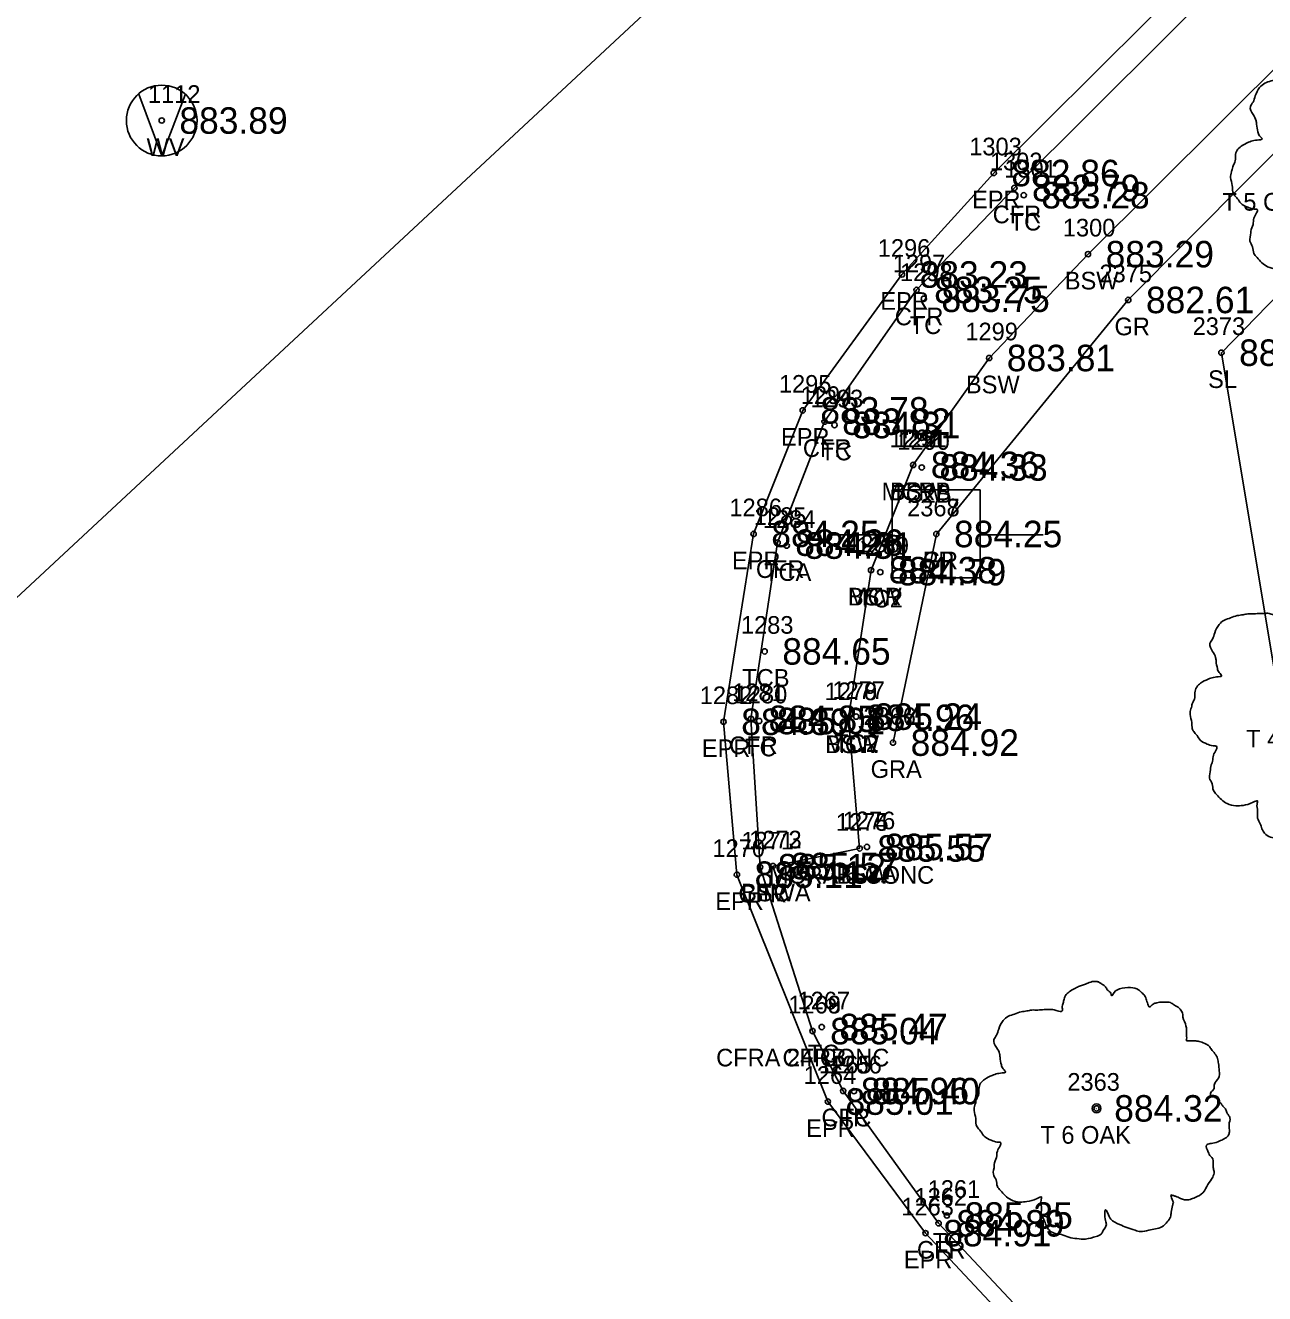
# Model space of a CAD drawing. Extents: x 1622501 to 1626664, y 1117816 to 1121579.
# Drawn here: x 1623634 to 1623704.2, y 1118887.8 to 1118959.6 of the extents above; entities that cross this region are included whole.
import ezdxf

# ---------------------------------------------------------------- set-up
doc = ezdxf.new("R2010")
doc.units = 0
for name, color, linetype in [('RD_EX_Conc', 7, 'Continuous'), ('RD_EX_Conc_txCode', 7, 'Continuous'), ('RD_EX_GuardRail', 7, 'Continuous'), ('RD_EX_GuardRail_txCode', 7, 'Continuous'), ('RD_EX_Road', 7, 'Continuous'), ('RD_EX_Road_txCode', 7, 'Continuous'), ('RD_EX_TX_Conc_ELEV', 7, 'Continuous'), ('RD_EX_TX_GuardRail_ELEV', 7, 'Continuous'), ('RD_EX_TX_Road_ELEV', 7, 'Continuous'), ('RD_EX_TX_UT_ELEV', 7, 'Continuous'), ('RD_EX_TX_VEG_ELEV', 7, 'Continuous'), ('RD_EX_UT', 7, 'Continuous'), ('RD_EX_UT_txCode', 7, 'Continuous'), ('RD_EX_VEG', 7, 'Continuous'), ('RD_EX_VEG_txCode', 7, 'Continuous'), ('RD_HC_Cl', 7, 'Continuous'), ('RD_HC_Survey_ELEV', 7, 'Continuous'), ('RD_SMD_Locator', 7, 'Continuous')]:
    doc.layers.add(name, color=color, linetype=linetype)

msp = doc.modelspace()

# ---------------------------------------------------------------- linework, layer by layer
at = {"layer": 'RD_EX_Conc'}
for points in [[(1623723.663, 1118851.276), (1623685.686, 1118891.781), (1623680.278, 1118899.276), (1623678.543, 1118902.667), (1623678.543, 1118902.667), (1623675.573, 1118911.952), (1623675.054, 1118920.354), (1623676.566, 1118930.331), (1623679.225, 1118937.184), (1623684.435, 1118944.641), (1623689.976, 1118950.418), (1623724.501, 1118984.8), (1623759.009, 1119020.42), (1623793.698, 1119055.906), (1623829.35, 1119090.862), (1623865.612, 1119125.129), (1623901.916, 1119159.181), (1623933.224, 1119188.498)], [(1623676.299, 1118912.014), (1623681.213, 1118913.011), (1623680.576, 1118920.41), (1623681.86, 1118928.773), (1623684.243, 1118934.734), (1623688.548, 1118940.788), (1623694.147, 1118946.67), (1623728.265, 1118980.628), (1623762.622, 1119016.068), (1623797.565, 1119051.919), (1623833.104, 1119086.631), (1623869.148, 1119120.8), (1623905.547, 1119154.999), (1623936.969, 1119184.346), (1623933.79, 1119188.026)], [(1623681.213, 1118913.011), (1623680.576, 1118920.41), (1623681.86, 1118928.773), (1623684.243, 1118934.734)]]:
    msp.add_lwpolyline(points, dxfattribs=at)
at = {"layer": 'RD_EX_GuardRail'}
msp.add_lwpolyline([(1623683.102, 1118919.005), (1623685.557, 1118930.82), (1623696.428, 1118944.075), (1623730.666, 1118978.537), (1623766.322, 1119014.094)], dxfattribs=at)
at = {"layer": 'RD_EX_Road'}
msp.add_lwpolyline([(1623722.97, 1118850.612), (1623684.945, 1118891.225), (1623679.413, 1118898.675), (1623674.261, 1118911.526), (1623673.503, 1118920.185), (1623675.206, 1118930.826), (1623677.985, 1118937.822), (1623683.61, 1118945.518), (1623688.806, 1118951.265), (1623723.469, 1118985.717), (1623758.003, 1119021.43), (1623792.693, 1119056.92), (1623828.408, 1119091.915), (1623864.599, 1119126.191), (1623900.882, 1119160.216), (1623932.37, 1119189.416), (1623932.628, 1119189.219), (1623935.818, 1119192.17), (1623973.771, 1119227.767), (1623990.875, 1119243.538), (1624009.987, 1119262.018), (1624046.295, 1119296.153)], dxfattribs=at)
at = {"layer": 'RD_EX_UT'}
for p, q in [((1623641.68, 1118952.244), (1623640.376, 1118955.727)), ((1623641.68, 1118952.244), (1623643.002, 1118955.689)), ((1623688.047, 1118933.329), (1623683.047, 1118933.329)), ((1623683.047, 1118933.329), (1623683.047, 1118928.329)), ((1623688.047, 1118928.329), (1623688.047, 1118933.329)), ((1623679.616, 1118930.767), (1623683.086, 1118930.767)), ((1623687.976, 1118930.767), (1623691.616, 1118930.767)), ((1623683.047, 1118928.329), (1623688.047, 1118928.329))]:
    msp.add_line(p, q, dxfattribs=at)
msp.add_circle((1623641.68, 1118954.237), 2, dxfattribs=at)
at = {"layer": 'RD_EX_VEG'}
msp.add_lwpolyline([(1623719.641, 1118895.843), (1623705.963, 1118915.58), (1623701.704, 1118941.089), (1623733.735, 1118974.045), (1623762.596, 1118998.968), (1623764.149, 1118997.606), (1623773.667, 1119008.214), (1623809.616, 1119040.562), (1623866.904, 1119093.207), (1623868.266, 1119096.09), (1623881.794, 1119107.882), (1623919.645, 1119143.849), (1623945.126, 1119165.729), (1623961.583, 1119122.835), (1623970.119, 1119088.038)], dxfattribs=at)
for centre, radius in [((1623694.631, 1118898.29), 0.25), ((1623694.618, 1118898.271), 0.0001)]:
    msp.add_circle(centre, radius, dxfattribs=at)
for points in [[(1623709.292, 1118958.301), (1623708.992, 1118958.326), (1623708.668, 1118958.226), (1623708.418, 1118958.126), (1623708.193, 1118958.051), (1623707.968, 1118957.951), (1623707.668, 1118957.776), (1623707.443, 1118957.576), (1623707.318, 1118957.326), (1623707.268, 1118957.102), (1623707.218, 1118956.827), (1623707.218, 1118956.652), (1623707.093, 1118956.627), (1623706.943, 1118956.652), (1623706.693, 1118956.727), (1623706.444, 1118956.727), (1623706.194, 1118956.727), (1623705.844, 1118956.702), (1623705.494, 1118956.702), (1623705.219, 1118956.652), (1623704.894, 1118956.602), (1623704.519, 1118956.477), (1623704.17, 1118956.352), (1623703.87, 1118956.102), (1623703.62, 1118955.627), (1623703.495, 1118955.277), (1623703.345, 1118955.027), (1623703.495, 1118954.578), (1623703.67, 1118954.228), (1623703.695, 1118954.028), (1623703.77, 1118953.603), (1623703.87, 1118953.378), (1623703.995, 1118953.178), (1623703.92, 1118953.153), (1623703.545, 1118953.103), (1623703.245, 1118953.003), (1623702.82, 1118952.778), (1623702.595, 1118952.554), (1623702.495, 1118952.229), (1623702.47, 1118951.879), (1623702.37, 1118951.679), (1623702.295, 1118951.404), (1623702.27, 1118951.329), (1623702.22, 1118951.004), (1623702.32, 1118950.554), (1623702.345, 1118950.205), (1623702.47, 1118949.98), (1623702.62, 1118949.805), (1623702.795, 1118949.555), (1623703.195, 1118949.33), (1623703.52, 1118949.23), (1623703.72, 1118949.205), (1623703.545, 1118948.705), (1623703.495, 1118948.355), (1623703.37, 1118947.956), (1623703.37, 1118947.881), (1623703.32, 1118947.406), (1623703.47, 1118947.081), (1623703.545, 1118946.706), (1623703.72, 1118946.481), (1623703.995, 1118946.181), (1623704.319, 1118945.956), (1623704.819, 1118945.831), (1623705.219, 1118945.856), (1623705.794, 1118946.031), (1623706.044, 1118946.106), (1623706.019, 1118945.931), (1623706.044, 1118945.557), (1623706.044, 1118945.132), (1623706.194, 1118944.807), (1623706.294, 1118944.532), (1623706.444, 1118944.282), (1623706.768, 1118944.057), (1623707.168, 1118943.982), (1623707.593, 1118943.832), (1623708.043, 1118943.757), (1623708.543, 1118943.732), (1623709.142, 1118943.882), (1623709.417, 1118944.007), (1623709.517, 1118944.182), (1623709.717, 1118944.557), (1623709.667, 1118944.782), (1623709.692, 1118945.382), (1623709.792, 1118945.207), (1623709.967, 1118944.857), (1623710.467, 1118944.557), (1623710.867, 1118944.382), (1623711.341, 1118944.232), (1623711.641, 1118944.157), (1623712.116, 1118944.232), (1623712.491, 1118944.307), (1623712.866, 1118944.432), (1623713.166, 1118944.707), (1623713.341, 1118944.982), (1623713.391, 1118945.257), (1623713.465, 1118945.632), (1623713.515, 1118945.806)], [(1623707, 1118927.896), (1623706.7, 1118927.921), (1623706.375, 1118927.821), (1623706.125, 1118927.721), (1623705.9, 1118927.646), (1623705.676, 1118927.546), (1623705.376, 1118927.371), (1623705.151, 1118927.171), (1623705.026, 1118926.921), (1623704.976, 1118926.697), (1623704.926, 1118926.422), (1623704.926, 1118926.247), (1623704.801, 1118926.222), (1623704.651, 1118926.247), (1623704.401, 1118926.322), (1623704.151, 1118926.322), (1623703.901, 1118926.322), (1623703.551, 1118926.297), (1623703.202, 1118926.297), (1623702.927, 1118926.247), (1623702.602, 1118926.197), (1623702.227, 1118926.072), (1623701.877, 1118925.947), (1623701.577, 1118925.697), (1623701.327, 1118925.222), (1623701.202, 1118924.872), (1623701.053, 1118924.622), (1623701.202, 1118924.173), (1623701.377, 1118923.823), (1623701.402, 1118923.623), (1623701.477, 1118923.198), (1623701.577, 1118922.973), (1623701.702, 1118922.773), (1623701.627, 1118922.748), (1623701.252, 1118922.698), (1623700.953, 1118922.598), (1623700.528, 1118922.373), (1623700.303, 1118922.149), (1623700.203, 1118921.824), (1623700.178, 1118921.474), (1623700.078, 1118921.274), (1623700.003, 1118920.999), (1623699.978, 1118920.924), (1623699.928, 1118920.599), (1623700.028, 1118920.149), (1623700.053, 1118919.8), (1623700.178, 1118919.575), (1623700.328, 1118919.4), (1623700.503, 1118919.15), (1623700.903, 1118918.925), (1623701.227, 1118918.825), (1623701.427, 1118918.8), (1623701.252, 1118918.3), (1623701.202, 1118917.95), (1623701.078, 1118917.551), (1623701.078, 1118917.476), (1623701.028, 1118917.001), (1623701.177, 1118916.676), (1623701.252, 1118916.301), (1623701.427, 1118916.076), (1623701.702, 1118915.776), (1623702.027, 1118915.551), (1623702.527, 1118915.426), (1623702.927, 1118915.451), (1623703.502, 1118915.626), (1623703.751, 1118915.701), (1623703.726, 1118915.526), (1623703.751, 1118915.152), (1623703.751, 1118914.727), (1623703.901, 1118914.402), (1623704.001, 1118914.127), (1623704.151, 1118913.877), (1623704.476, 1118913.652), (1623704.876, 1118913.577), (1623705.301, 1118913.427), (1623705.751, 1118913.352), (1623706.25, 1118913.327), (1623706.85, 1118913.477), (1623707.125, 1118913.602), (1623707.225, 1118913.777), (1623707.425, 1118914.152), (1623707.375, 1118914.377), (1623707.4, 1118914.977), (1623707.5, 1118914.802), (1623707.675, 1118914.452), (1623708.174, 1118914.152), (1623708.574, 1118913.977), (1623709.049, 1118913.827), (1623709.349, 1118913.752), (1623709.824, 1118913.827), (1623710.199, 1118913.902), (1623710.573, 1118914.027), (1623710.873, 1118914.302), (1623711.048, 1118914.577), (1623711.098, 1118914.852), (1623711.173, 1118915.227), (1623711.223, 1118915.401)], [(1623694.763, 1118905.457), (1623694.463, 1118905.482), (1623694.138, 1118905.382), (1623693.888, 1118905.282), (1623693.663, 1118905.207), (1623693.438, 1118905.107), (1623693.138, 1118904.933), (1623692.913, 1118904.733), (1623692.788, 1118904.483), (1623692.738, 1118904.258), (1623692.689, 1118903.983), (1623692.689, 1118903.808), (1623692.564, 1118903.783), (1623692.414, 1118903.808), (1623692.164, 1118903.883), (1623691.914, 1118903.883), (1623691.664, 1118903.883), (1623691.314, 1118903.858), (1623690.964, 1118903.858), (1623690.689, 1118903.808), (1623690.365, 1118903.758), (1623689.99, 1118903.633), (1623689.64, 1118903.508), (1623689.34, 1118903.258), (1623689.09, 1118902.784), (1623688.965, 1118902.434), (1623688.815, 1118902.184), (1623688.965, 1118901.734), (1623689.14, 1118901.384), (1623689.165, 1118901.184), (1623689.24, 1118900.759), (1623689.34, 1118900.535), (1623689.465, 1118900.335), (1623689.39, 1118900.31), (1623689.015, 1118900.26), (1623688.715, 1118900.16), (1623688.29, 1118899.935), (1623688.066, 1118899.71), (1623687.966, 1118899.385), (1623687.941, 1118899.035), (1623687.841, 1118898.835), (1623687.766, 1118898.56), (1623687.741, 1118898.485), (1623687.691, 1118898.161), (1623687.791, 1118897.711), (1623687.816, 1118897.361), (1623687.941, 1118897.136), (1623688.091, 1118896.961), (1623688.265, 1118896.711), (1623688.665, 1118896.486), (1623688.99, 1118896.386), (1623689.19, 1118896.361), (1623689.015, 1118895.862), (1623688.965, 1118895.512), (1623688.84, 1118895.112), (1623688.84, 1118895.037), (1623688.79, 1118894.562), (1623688.94, 1118894.237), (1623689.015, 1118893.862), (1623689.19, 1118893.638), (1623689.465, 1118893.338), (1623689.79, 1118893.113), (1623690.29, 1118892.988), (1623690.689, 1118893.013), (1623691.264, 1118893.188), (1623691.514, 1118893.263), (1623691.489, 1118893.088), (1623691.514, 1118892.713), (1623691.514, 1118892.288), (1623691.664, 1118891.963), (1623691.764, 1118891.688), (1623691.914, 1118891.438), (1623692.239, 1118891.214), (1623692.639, 1118891.139), (1623693.063, 1118890.989), (1623693.513, 1118890.914), (1623694.013, 1118890.889), (1623694.613, 1118891.039), (1623694.888, 1118891.164), (1623694.988, 1118891.339), (1623695.187, 1118891.713), (1623695.137, 1118891.938), (1623695.162, 1118892.538), (1623695.262, 1118892.363), (1623695.437, 1118892.013), (1623695.937, 1118891.713), (1623696.337, 1118891.538), (1623696.812, 1118891.388), (1623697.112, 1118891.314), (1623697.586, 1118891.388), (1623697.961, 1118891.463), (1623698.336, 1118891.588), (1623698.636, 1118891.863), (1623698.811, 1118892.138), (1623698.861, 1118892.413), (1623698.936, 1118892.788), (1623698.986, 1118892.963)], [(1623698.986, 1118892.963), (1623698.911, 1118893.138), (1623698.861, 1118893.388), (1623698.936, 1118893.363), (1623699.111, 1118893.313), (1623699.386, 1118893.188), (1623699.611, 1118893.113), (1623699.935, 1118893.138), (1623700.21, 1118893.238), (1623700.66, 1118893.513), (1623700.935, 1118893.987), (1623701.21, 1118894.387), (1623701.285, 1118894.712), (1623701.235, 1118894.937), (1623701.21, 1118895.437), (1623701.01, 1118895.687), (1623700.96, 1118895.812), (1623700.86, 1118896.211), (1623700.935, 1118896.261), (1623701.21, 1118896.311), (1623701.585, 1118896.436), (1623701.86, 1118896.561), (1623702.084, 1118896.736), (1623702.159, 1118896.961), (1623702.134, 1118897.361), (1623702.184, 1118897.761), (1623702.109, 1118897.911), (1623702.009, 1118898.061), (1623701.934, 1118898.261), (1623701.785, 1118898.41), (1623701.685, 1118898.56), (1623701.585, 1118898.66), (1623701.46, 1118898.81), (1623701.285, 1118898.935), (1623701.135, 1118898.985), (1623701.085, 1118899.135), (1623701.235, 1118899.335), (1623701.285, 1118899.435), (1623701.31, 1118899.66), (1623701.535, 1118900.01), (1623701.585, 1118900.41), (1623701.535, 1118900.834), (1623701.485, 1118901.109), (1623701.335, 1118901.384), (1623701.135, 1118901.634), (1623701.01, 1118901.809), (1623700.835, 1118901.934), (1623700.51, 1118902.059), (1623700.26, 1118902.109), (1623699.91, 1118902.109), (1623699.71, 1118902.159), (1623699.735, 1118902.209), (1623699.735, 1118902.359), (1623699.735, 1118902.634), (1623699.66, 1118903.083), (1623699.511, 1118903.583), (1623699.511, 1118903.608), (1623699.411, 1118903.858), (1623699.186, 1118904.058), (1623699.011, 1118904.158), (1623698.811, 1118904.283), (1623698.561, 1118904.308), (1623698.261, 1118904.308), (1623697.986, 1118904.258), (1623697.786, 1118904.158), (1623697.611, 1118904.033), (1623697.536, 1118904.183), (1623697.436, 1118904.483), (1623697.386, 1118904.633), (1623697.237, 1118904.808), (1623697.012, 1118905.008), (1623696.562, 1118905.132), (1623695.937, 1118905.058), (1623695.637, 1118904.858), (1623695.487, 1118904.683), (1623695.437, 1118904.808), (1623695.237, 1118905.008), (1623695.137, 1118905.182), (1623694.963, 1118905.307), (1623694.813, 1118905.407), (1623694.713, 1118905.457)]]:
    msp.add_spline(points, degree=3, dxfattribs=at)
at = {"layer": 'RD_HC_Cl'}
msp.add_line((1623608.837, 1118904.32), (1623937.248, 1119209.793), dxfattribs=at)
at = {"layer": 'RD_SMD_Locator'}
for centre in [(1623641.68, 1118954.237), (1623688.806, 1118951.265), (1623689.976, 1118950.418), (1623690.506, 1118950.007), (1623694.147, 1118946.67), (1623683.61, 1118945.518), (1623684.435, 1118944.641), (1623684.846, 1118944.144), (1623696.428, 1118944.075), (1623701.704, 1118941.089), (1623688.548, 1118940.788), (1623677.985, 1118937.822), (1623679.225, 1118937.184), (1623679.787, 1118936.992), (1623684.243, 1118934.734), (1623684.243, 1118934.734), (1623684.729, 1118934.589), (1623675.206, 1118930.826), (1623685.557, 1118930.82), (1623685.557, 1118930.82), (1623676.566, 1118930.331), (1623677.083, 1118930.164), (1623681.86, 1118928.773), (1623681.86, 1118928.773), (1623682.38, 1118928.661), (1623675.833, 1118924.171), (1623673.503, 1118920.185), (1623675.054, 1118920.354), (1623675.523, 1118920.229), (1623680.576, 1118920.41), (1623680.576, 1118920.41), (1623681.017, 1118920.478), (1623683.102, 1118919.005), (1623681.213, 1118913.011), (1623681.213, 1118913.011), (1623681.625, 1118913.097), (1623674.261, 1118911.526), (1623675.573, 1118911.952), (1623676.299, 1118912.014), (1623676.299, 1118912.014), (1623679.065, 1118902.897), (1623678.543, 1118902.667), (1623678.543, 1118902.667), (1623680.278, 1118899.276), (1623680.888, 1118899.267), (1623679.413, 1118898.675), (1623694.631, 1118898.29), (1623686.153, 1118892.223), (1623685.686, 1118891.781), (1623684.945, 1118891.225)]:
    msp.add_circle(centre, 0.15, dxfattribs=at)

# ---------------------------------------------------------------- texts
at = {"layer": 'RD_EX_Conc_txCode'}
for s, p in [('1302', (1623688.59, 1118951.418)), ('1301', (1623689.404, 1118951.007)), ('CFR', (1623688.748, 1118948.418)), ('TC', (1623689.711, 1118948.007)), ('1300', (1623692.722, 1118947.67)), ('1297', (1623683.088, 1118945.641)), ('1298', (1623683.5, 1118945.144)), ('BSW', (1623692.832, 1118944.67)), ('CFR', (1623683.206, 1118942.641)), ('TC', (1623684.051, 1118942.144)), ('1299', (1623687.201, 1118941.788)), ('BSW', (1623687.233, 1118938.788)), ('1294', (1623677.879, 1118938.184)), ('1293', (1623678.44, 1118937.992)), ('1292', (1623682.896, 1118935.734)), ('1291', (1623683.18, 1118935.734)), ('CFR', (1623677.997, 1118935.184)), ('TC', (1623678.992, 1118934.992)), ('1290', (1623683.343, 1118935.589)), ('MCRB', (1623682.455, 1118932.734)), ('BSW', (1623682.928, 1118932.734)), ('TC2B', (1623683.012, 1118932.589)), ('1285', (1623675.219, 1118931.331)), ('1284', (1623675.736, 1118931.164)), ('1287', (1623680.513, 1118929.773)), ('1288', (1623680.513, 1118929.773)), ('1289', (1623681.034, 1118929.661)), ('CFR', (1623675.337, 1118928.331)), ('TCA', (1623675.799, 1118928.164)), ('MCR', (1623680.545, 1118926.773)), ('BSW', (1623680.545, 1118926.773)), ('TC2', (1623681.136, 1118926.661)), ('1283', (1623674.487, 1118925.171)), ('TCB', (1623674.565, 1118922.171)), ('1281', (1623673.991, 1118921.354)), ('1278', (1623679.229, 1118921.41)), ('1279', (1623679.229, 1118921.41)), ('1277', (1623679.67, 1118921.478)), ('1280', (1623674.137, 1118921.229)), ('MCR', (1623679.261, 1118918.41)), ('BSW', (1623679.261, 1118918.41)), ('TC2', (1623679.773, 1118918.478)), ('CFR', (1623673.826, 1118918.354)), ('TC', (1623674.728, 1118918.229)), ('1276', (1623680.255, 1118914.097)), ('1274', (1623679.866, 1118914.011)), ('1275', (1623679.866, 1118914.011)), ('1271', (1623674.51, 1118912.952)), ('1272', (1623674.953, 1118913.014)), ('1273', (1623674.953, 1118913.014)), ('MCRA 6 CONC', (1623676.071, 1118911.011)), ('TC2A', (1623679.893, 1118911.097)), ('BSW', (1623679.898, 1118911.011)), ('CFR', (1623674.345, 1118909.952)), ('BSWA', (1623674.496, 1118910.014)), ('TC', (1623675.504, 1118910.014)), ('1268', (1623677.173, 1118903.667)), ('1269', (1623677.173, 1118903.667)), ('1267', (1623677.695, 1118903.897)), ('CFRA 24 CONC', (1623673.086, 1118900.667)), ('CFRB', (1623676.842, 1118900.667)), ('TC', (1623678.27, 1118900.897)), ('1265', (1623678.908, 1118900.276)), ('1266', (1623679.494, 1118900.267)), ('CFR', (1623679.05, 1118897.276)), ('TC', (1623680.093, 1118897.267)), ('1262', (1623684.316, 1118892.781)), ('1261', (1623685.066, 1118893.223)), ('CFR', (1623684.457, 1118889.781)), ('TC', (1623685.357, 1118890.223))]:
    msp.add_text(s, height=1, dxfattribs=at).set_placement(p)
at = {"layer": 'RD_EX_GuardRail_txCode'}
for s, p in [('2375', (1623694.798, 1118945.075)), ('GR', (1623695.648, 1118942.075)), ('2367', (1623683.903, 1118931.82)), ('GR', (1623684.777, 1118928.82)), ('2366', (1623681.424, 1118920.005)), ('GRA', (1623681.834, 1118917.005))]:
    msp.add_text(s, height=1, dxfattribs=at).set_placement(p)
at = {"layer": 'RD_EX_Road_txCode'}
for s, p in [('1303', (1623687.42, 1118952.265)), ('EPR', (1623687.578, 1118949.265)), ('1296', (1623682.24, 1118946.518)), ('EPR', (1623682.382, 1118943.518)), ('1295', (1623676.639, 1118938.822)), ('EPR', (1623676.757, 1118935.822)), ('1286', (1623673.836, 1118931.826)), ('EPR', (1623673.978, 1118928.826)), ('1282', (1623672.157, 1118921.185)), ('EPR', (1623672.275, 1118918.185)), ('1270', (1623672.875, 1118912.526)), ('EPR', (1623673.033, 1118909.526)), ('1264', (1623678.043, 1118899.675)), ('EPR', (1623678.185, 1118896.675)), ('1263', (1623683.575, 1118892.225)), ('EPR', (1623683.717, 1118889.225))]:
    msp.add_text(s, height=1, dxfattribs=at).set_placement(p)
at = {"layer": 'RD_EX_TX_Conc_ELEV'}
for s, p in [('882.79', (1623690.976, 1118949.668)), ('883.28', (1623691.506, 1118949.257)), ('883.29', (1623695.147, 1118945.92)), ('883.25', (1623685.435, 1118943.891)), ('883.75', (1623685.846, 1118943.394)), ('883.81', (1623689.548, 1118940.038)), ('883.82', (1623680.225, 1118936.434)), ('884.31', (1623680.787, 1118936.242)), ('884.36', (1623685.243, 1118933.984)), ('884.36', (1623685.243, 1118933.984)), ('884.33', (1623685.729, 1118933.839)), ('884.26', (1623677.566, 1118929.581)), ('884.31', (1623678.083, 1118929.414)), ('884.38', (1623682.86, 1118928.023)), ('884.38', (1623682.86, 1118928.023)), ('884.79', (1623683.38, 1118927.911)), ('884.65', (1623676.833, 1118923.421)), ('884.85', (1623676.054, 1118919.604)), ('885.01', (1623676.523, 1118919.479)), ('884.96', (1623681.576, 1118919.66)), ('884.96', (1623681.576, 1118919.66)), ('885.24', (1623682.017, 1118919.728)), ('885.55', (1623682.213, 1118912.261)), ('885.55', (1623682.213, 1118912.261)), ('885.57', (1623682.625, 1118912.347)), ('885.12', (1623676.573, 1118911.202)), ('885.57', (1623677.299, 1118911.264)), ('885.57', (1623677.299, 1118911.264)), ('885.47', (1623680.065, 1118902.147)), ('885.04', (1623679.543, 1118901.917)), ('885.04', (1623679.543, 1118901.917)), ('884.96', (1623681.278, 1118898.526)), ('885.40', (1623681.888, 1118898.517)), ('885.35', (1623687.153, 1118891.473)), ('884.89', (1623686.686, 1118891.031))]:
    msp.add_text(s, height=1.5, dxfattribs=at).set_placement(p)
at = {"layer": 'RD_EX_TX_GuardRail_ELEV'}
for s, p in [('882.61', (1623697.428, 1118943.325)), ('884.25', (1623686.557, 1118930.07)), ('884.92', (1623684.102, 1118918.255))]:
    msp.add_text(s, height=1.5, dxfattribs=at).set_placement(p)
at = {"layer": 'RD_EX_TX_Road_ELEV'}
for s, p in [('882.86', (1623689.806, 1118950.515)), ('883.23', (1623684.61, 1118944.768)), ('883.78', (1623678.985, 1118937.072)), ('884.25', (1623676.206, 1118930.076)), ('884.89', (1623674.503, 1118919.435)), ('885.11', (1623675.261, 1118910.776)), ('885.01', (1623680.413, 1118897.925)), ('884.91', (1623685.945, 1118890.475))]:
    msp.add_text(s, height=1.5, dxfattribs=at).set_placement(p)
at = {"layer": 'RD_EX_TX_UT_ELEV'}
msp.add_text('883.89', height=1.5, dxfattribs=at).set_placement((1623642.68, 1118953.487))
at = {"layer": 'RD_EX_TX_VEG_ELEV'}
for s, p in [('882.19', (1623702.704, 1118940.339)), ('884.32', (1623695.631, 1118897.54))]:
    msp.add_text(s, height=1.5, dxfattribs=at).set_placement(p)
at = {"layer": 'RD_EX_UT_txCode'}
for s, p in [('1112', (1623640.9, 1118955.237)), ('WV', (1623640.822, 1118952.237)), ('2368', (1623683.903, 1118931.82)), ('PP', (1623684.777, 1118928.82))]:
    msp.add_text(s, height=1, dxfattribs=at).set_placement(p)
at = {"layer": 'RD_EX_VEG_txCode'}
for s, p in [('T 5 CRAPE MYRTLE', (1623701.755, 1118949.134)), ('2373', (1623700.074, 1118942.089)), ('SL', (1623700.948, 1118939.089)), ('T 4 TULIP', (1623703.104, 1118918.729)), ('2363', (1623692.977, 1118899.29)), ('T 6 OAK', (1623691.45, 1118896.29))]:
    msp.add_text(s, height=1, dxfattribs=at).set_placement(p)
at = {"layer": 'RD_HC_Survey_ELEV'}
msp.add_text('884.25', height=1.5, dxfattribs=at).set_placement((1623686.557, 1118930.07))

doc.saveas('drawing.dxf')
